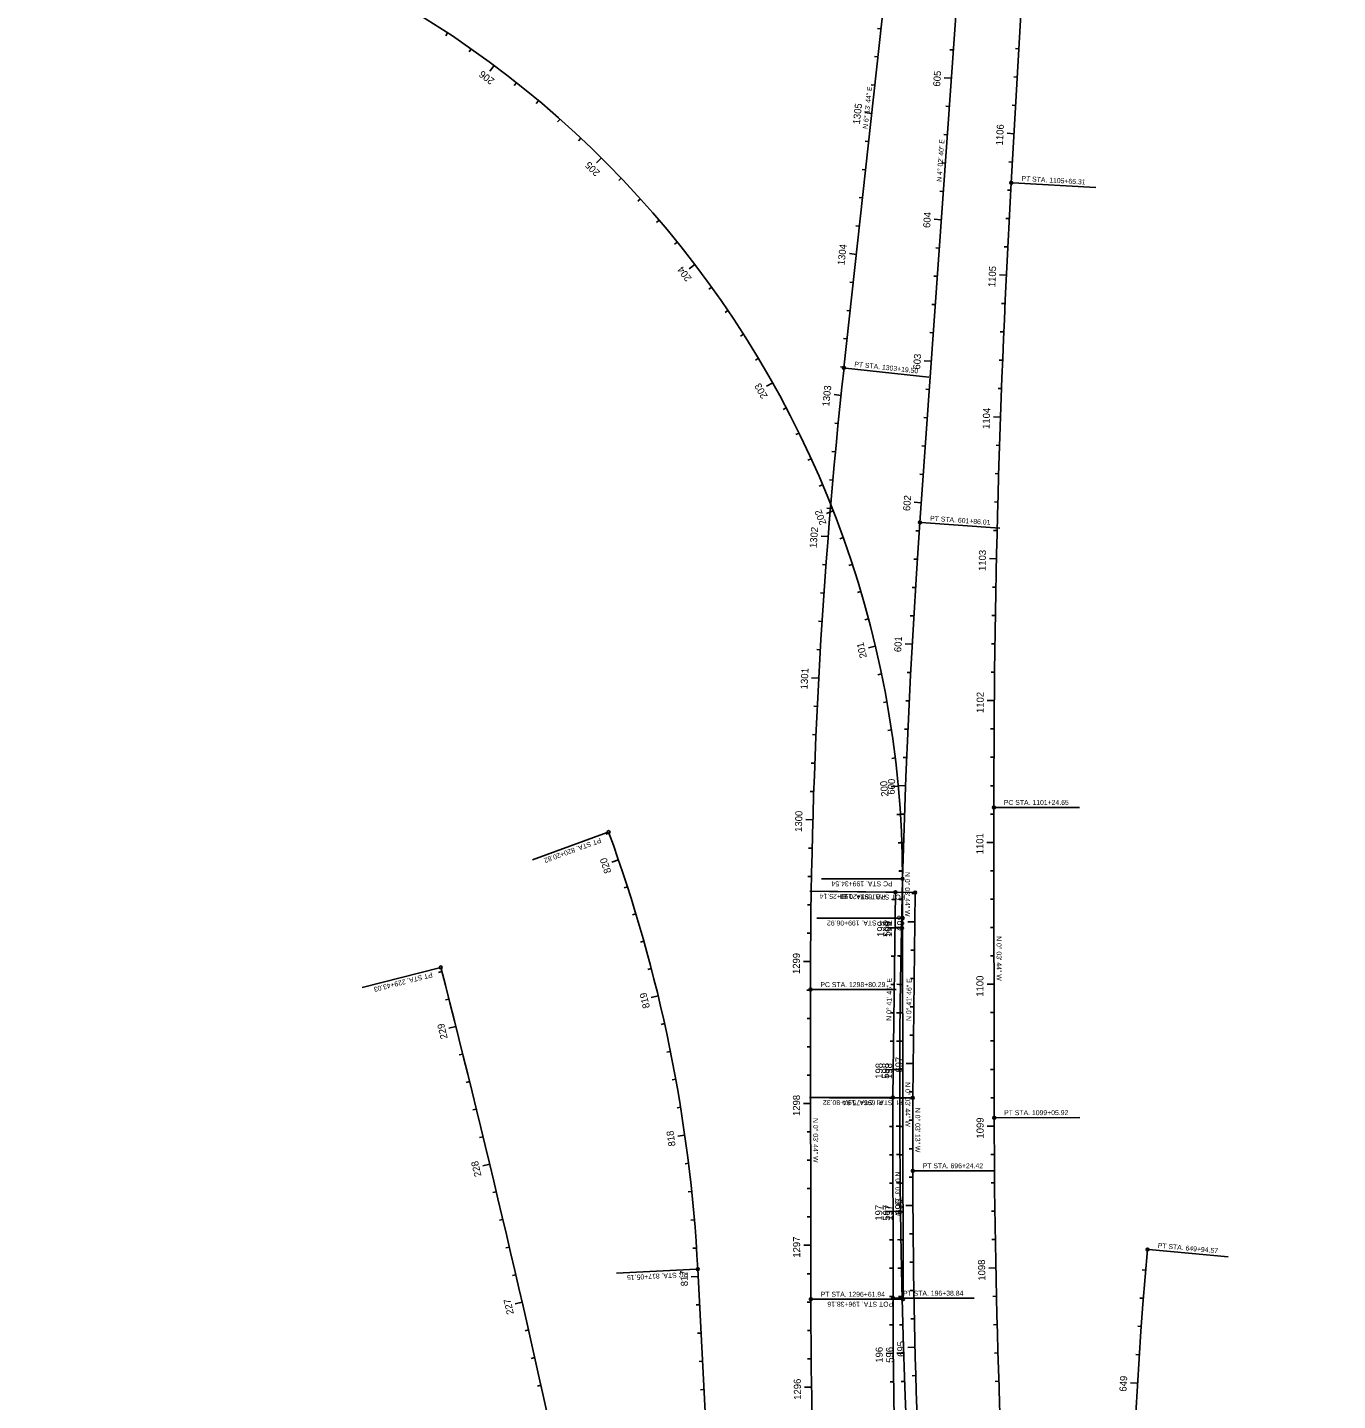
# Model space of a CAD drawing. Extents: x 919452 to 931278, y 583254 to 665650.
# Drawn here: x 928370 to 929294, y 635415 to 636383 of the extents above; entities that cross this region are included whole.
import ezdxf

# ---------------------------------------------------------------- set-up
doc = ezdxf.new("R2010")
doc.units = 0
for name, color, linetype in [('CLConst_dp', 7, 'Continuous'), ('CurveDataLabel_dp', 7, 'Continuous'), ('StationTicL_dp', 7, 'Continuous'), ('StationTicS_dp', 7, 'Continuous'), ('TextBLStation', 7, 'Continuous'), ('TextLabel', 7, 'Continuous')]:
    doc.layers.add(name, color=color, linetype=linetype)

msp = doc.modelspace()

# ---------------------------------------------------------------- linework, layer by layer
at = {"layer": 'CLConst_dp'}
for p, q in [((929063.91, 636273.75), (929152.38, 637830.35)), ((928999.45, 636034.27), (929035.97, 636550.78)), ((928945.89, 636143.25), (928986.58, 636516.04)), ((929051.88, 635614.6), (929051.64, 635833.32)), ((928987.22, 635755.38), (928987.19, 635783.01)), ((928980.38, 635628.77), (928982.14, 635773.59)), ((928994.38, 635628.7), (928996.14, 635773.42)), ((928987.51, 635486.62), (928987.22, 635755.38)), ((928922.51, 635486.55), (928922.28, 635704.9)), ((928980.51, 635487.29), (928980.38, 635628.77)), ((928994.43, 635577.17), (928994.38, 635628.7)), ((928856.53, 635243.73), (928842.76, 635507.87))]:
    msp.add_line(p, q, dxfattribs=at)
for centre, radius, start, end in [((928270.99, 635782.23), 716.2, 0.06217, 82.06007), ((936667.07, 635841.59), 7615.44, 176.746791, 180.062174), ((932922.28, 635709.24), 4000, 173.771, 180.06217), ((934714.76, 635630.15), 5729.58, 175.955434, 198.89818), ((927786.65, 635452.81), 1057.54, 2.98469, 20.08694), ((919023.27, 633253.37), 9949, 9.590734, 14.358327), ((934757.45, 635620.79), 5705.58, 180.06217, 188.19915), ((934313.46, 635582.15), 5319.04, 180.05369, 188.30596), ((932014.36, 635260.36), 2866.29, 174.76849, 187.10964), ((933567.21, 635491.59), 4644.7, 180.06217, 187.81416), ((933567.17, 635491.59), 4586.66, 180.05369, 186.8847)]:
    msp.add_arc(centre, radius, start, end, dxfattribs=at)
at = {"layer": 'CurveDataLabel_dp'}
for p, q in [((929064.9, 636273.7), (929123.58, 636270.36)), ((928946.88, 636143.15), (929005.84, 636136.71)), ((929000.44, 636034.2), (929055.93, 636030.28)), ((929052.64, 635833.32), (929112.1, 635833.39)), ((928778.92, 635815.67), (928726.09, 635796.35)), ((928986.19, 635783), (928929.99, 635782.94)), ((928981.14, 635773.6), (928921.85, 635774.32)), ((928995.14, 635773.43), (928935.73, 635774.15)), ((928986.22, 635755.38), (928926.79, 635755.32)), ((928660.53, 635720.33), (928606.03, 635706.38)), ((928923.28, 635704.9), (928982.69, 635704.97)), ((928979.38, 635628.77), (928921.6, 635628.72)), ((928993.38, 635628.69), (928935.74, 635628.64)), ((929052.88, 635614.6), (929112.27, 635614.66)), ((928995.43, 635577.17), (929051.68, 635577.22)), ((929161.01, 635521.62), (929216.87, 635516.5)), ((928841.76, 635507.82), (928785.52, 635504.89)), ((928923.51, 635486.55), (928982.77, 635486.62)), ((928986.51, 635486.62), (928927.15, 635486.56)), ((928981.51, 635487.29), (929037.63, 635487.35))]:
    msp.add_line(p, q, dxfattribs=at)
for centre in [(929063.91, 636273.75), (928945.89, 636143.25), (928999.45, 636034.27), (929051.64, 635833.32), (928779.86, 635816.01), (928987.19, 635783.01), (928982.14, 635773.59), (928996.14, 635773.42), (928987.22, 635755.38), (928661.5, 635720.58), (928922.28, 635704.9), (928980.38, 635628.77), (928994.38, 635628.7), (929051.88, 635614.6), (928994.43, 635577.17), (929160.01, 635521.71), (928842.76, 635507.87), (928922.51, 635486.55), (928980.51, 635487.29), (928987.51, 635486.62)]:
    msp.add_circle(centre, 1, dxfattribs=at)
at = {"layer": 'StationTicL_dp'}
for p, q in [((928699.03, 636356.45), (928696.04, 636352.44)), ((929021.59, 636347.48), (929016.61, 636347.84)), ((928965.48, 636322.69), (928960.51, 636323.23)), ((929065.88, 636308.39), (929060.88, 636308.67)), ((928774.78, 636291.29), (928771.26, 636287.74)), ((929014.54, 636247.73), (929009.55, 636248.08)), ((928954.63, 636223.28), (928949.66, 636223.82)), ((928840.72, 636216.22), (928836.75, 636213.19)), ((929060.48, 636208.53), (929055.49, 636208.78)), ((929007.49, 636147.98), (929002.5, 636148.33)), ((928895.58, 636132.71), (928891.22, 636130.26)), ((928943.82, 636123.87), (928938.85, 636124.39)), ((929056.32, 636108.62), (929051.32, 636108.8)), ((929000.43, 636048.23), (928995.45, 636048.58)), ((928938.28, 636042.37), (928933.62, 636040.56)), ((928934.7, 636024.29), (928929.72, 636024.68)), ((929053.47, 636008.66), (929048.47, 636008.77)), ((928967.99, 635946.97), (928963.12, 635945.82)), ((928994.02, 635948.44), (928989.03, 635948.71)), ((928928.07, 635924.51), (928923.08, 635924.78)), ((929051.93, 635908.68), (929046.93, 635908.72)), ((928984.13, 635848.37), (928979.15, 635847.9)), ((928989.34, 635848.55), (928984.34, 635848.74)), ((928923.94, 635824.6), (928918.94, 635824.74)), ((929051.67, 635808.68), (929046.67, 635808.67)), ((928786.82, 635796.39), (928782.09, 635794.77)), ((928981.84, 635748.45), (928976.84, 635748.51)), ((928986.4, 635748.59), (928981.4, 635748.7)), ((928987.23, 635748.46), (928982.23, 635748.46)), ((928995.89, 635752.74), (928990.89, 635752.8)), ((928922.31, 635724.61), (928917.31, 635724.63)), ((929051.77, 635708.68), (929046.77, 635708.67)), ((928814.79, 635700.42), (928809.93, 635699.25)), ((928672.08, 635678.87), (928667.23, 635677.65)), ((928994.67, 635652.75), (928989.67, 635652.81)), ((928980.62, 635648.45), (928975.62, 635648.52)), ((928985.21, 635648.6), (928980.21, 635648.62)), ((928987.34, 635648.46), (928982.34, 635648.46)), ((928922.37, 635624.61), (928917.37, 635624.61)), ((928833.58, 635602.24), (928828.63, 635601.54)), ((929051.89, 635608.68), (929046.89, 635608.67)), ((928695.97, 635581.76), (928691.11, 635580.59)), ((928980.46, 635548.46), (928975.46, 635548.45)), ((928985.76, 635548.6), (928980.76, 635548.53)), ((928987.45, 635548.46), (928982.45, 635548.46)), ((928994.51, 635552.75), (928989.51, 635552.72)), ((928922.47, 635524.61), (928917.47, 635524.61)), ((929052.97, 635508.68), (929047.98, 635508.59)), ((928843.02, 635502.73), (928838.03, 635502.47)), ((928718.89, 635484.42), (928714.01, 635483.3)), ((928980.71, 635448.46), (928975.72, 635448.41)), ((928988.05, 635448.63), (928983.06, 635448.47)), ((928996, 635452.76), (928991, 635452.64)), ((929152.95, 635427.41), (929147.95, 635427.7)), ((928923, 635424.62), (928918, 635424.54))]:
    msp.add_line(p, q, dxfattribs=at)
at = {"layer": 'StationTicS_dp'}
for p, q in [((928666.31, 636379.45), (928664.93, 636377.36)), ((928971.99, 636382.34), (928969.5, 636382.61)), ((928682.83, 636368.18), (928681.39, 636366.13)), ((929023, 636367.43), (929020.51, 636367.61)), ((929069.28, 636368.29), (929066.78, 636368.43)), ((928969.82, 636362.46), (928967.33, 636362.73)), ((929068.15, 636348.32), (929065.65, 636348.47)), ((928714.89, 636344.27), (928713.35, 636342.31)), ((928967.65, 636342.57), (928965.16, 636342.84)), ((928730.41, 636331.66), (928728.81, 636329.74)), ((929020.18, 636327.53), (929017.69, 636327.71)), ((929067.01, 636328.36), (929064.51, 636328.5)), ((928745.58, 636318.62), (928743.92, 636316.74)), ((928760.37, 636305.16), (928758.66, 636303.33)), ((928963.31, 636302.81), (928960.82, 636303.08)), ((929018.77, 636307.58), (929016.28, 636307.76)), ((928961.14, 636282.93), (928958.65, 636283.2)), ((929017.36, 636287.63), (929014.87, 636287.81)), ((929064.74, 636288.42), (929062.24, 636288.56)), ((928788.8, 636277.02), (928786.99, 636275.3)), ((928802.41, 636262.37), (928800.55, 636260.7)), ((928958.97, 636263.05), (928956.48, 636263.32)), ((929015.95, 636267.68), (929013.46, 636267.86)), ((929063.61, 636268.45), (929061.11, 636268.59)), ((928815.61, 636247.35), (928813.71, 636245.72)), ((928956.8, 636243.16), (928954.31, 636243.43)), ((929062.51, 636248.48), (929060.02, 636248.62)), ((928828.38, 636231.96), (928826.44, 636230.39)), ((929013.13, 636227.78), (929010.64, 636227.96)), ((929061.47, 636228.51), (929058.97, 636228.64)), ((928952.46, 636203.4), (928949.97, 636203.67)), ((929011.72, 636207.83), (929009.23, 636208.01)), ((928852.62, 636200.14), (928850.59, 636198.69)), ((928864.06, 636183.74), (928861.99, 636182.34)), ((928950.29, 636183.52), (928947.8, 636183.79)), ((929010.31, 636187.88), (929007.81, 636188.06)), ((929059.54, 636188.56), (929057.05, 636188.67)), ((928875.04, 636167.03), (928872.93, 636165.68)), ((928948.12, 636163.64), (928945.63, 636163.91)), ((929008.9, 636167.93), (929006.4, 636168.11)), ((929058.66, 636168.58), (929056.16, 636168.68)), ((928885.55, 636150.01), (928883.4, 636148.73)), ((928945.95, 636143.75), (928943.46, 636144.03)), ((929057.82, 636148.59), (929055.33, 636148.69)), ((929006.08, 636128.03), (929003.58, 636128.21)), ((929057.04, 636128.61), (929054.55, 636128.7)), ((928905.12, 636115.13), (928902.91, 636113.97)), ((929004.67, 636108.08), (929002.17, 636108.26)), ((928914.17, 636097.3), (928911.92, 636096.2)), ((928941.8, 636103.97), (928939.31, 636104.22)), ((929003.25, 636088.13), (929000.76, 636088.31)), ((929055.64, 636088.63), (929053.14, 636088.71)), ((928922.72, 636079.21), (928920.44, 636078.18)), ((928939.88, 636084.06), (928937.39, 636084.3)), ((929001.84, 636068.18), (928999.35, 636068.36)), ((929055.02, 636068.64), (929052.52, 636068.72)), ((928930.75, 636060.9), (928928.45, 636059.93)), ((928938.05, 636064.15), (928935.56, 636064.37)), ((929054.45, 636048.65), (929051.95, 636048.72)), ((928936.33, 636044.22), (928933.84, 636044.43)), ((928999.03, 636028.28), (928996.53, 636028.45)), ((929053.93, 636028.66), (929051.43, 636028.72)), ((928945.28, 636023.64), (928942.93, 636022.8)), ((928997.67, 636008.33), (928995.18, 636008.49)), ((928933.18, 636004.34), (928930.68, 636004.53)), ((928951.76, 636004.72), (928949.38, 636003.94)), ((928996.39, 635988.37), (928993.89, 635988.52)), ((929053.05, 635988.67), (929050.56, 635988.72)), ((928931.75, 635984.4), (928929.26, 635984.57)), ((928957.71, 635985.62), (928955.31, 635984.91)), ((928930.42, 635964.44), (928927.93, 635964.6)), ((928963.12, 635966.37), (928960.7, 635965.73)), ((928995.17, 635968.4), (928992.67, 635968.55)), ((929052.69, 635968.67), (929050.19, 635968.71)), ((928929.2, 635944.48), (928926.7, 635944.62)), ((929052.39, 635948.67), (929049.89, 635948.71)), ((928972.32, 635927.45), (928969.87, 635926.94)), ((928992.95, 635928.47), (928990.45, 635928.6)), ((929052.13, 635928.67), (929049.63, 635928.7)), ((928927.05, 635904.54), (928924.55, 635904.66)), ((928976.1, 635907.81), (928973.64, 635907.37)), ((928991.94, 635908.49), (928989.44, 635908.61)), ((928926.12, 635884.56), (928923.62, 635884.67)), ((928979.33, 635888.07), (928976.86, 635887.7)), ((928991.01, 635888.51), (928988.51, 635888.63)), ((929051.78, 635888.68), (929049.28, 635888.69)), ((928925.29, 635864.57), (928922.79, 635864.67)), ((928982.01, 635868.25), (928979.53, 635867.95)), ((928990.14, 635868.53), (928987.64, 635868.64)), ((929051.68, 635868.68), (929049.18, 635868.69)), ((928924.57, 635844.59), (928922.07, 635844.67)), ((929051.64, 635848.68), (929049.14, 635848.68)), ((928985.7, 635828.43), (928983.21, 635828.27)), ((928988.61, 635828.56), (928986.12, 635828.65)), ((929051.64, 635828.68), (929049.14, 635828.67)), ((928780.14, 635815.24), (928777.79, 635814.39)), ((928923.41, 635804.6), (928920.91, 635804.66)), ((928986.71, 635808.45), (928984.21, 635808.36)), ((928987.96, 635808.57), (928985.46, 635808.65)), ((928987.17, 635788.46), (928984.67, 635788.44)), ((928987.37, 635788.58), (928984.87, 635788.65)), ((929051.69, 635788.68), (929049.19, 635788.67)), ((928793.14, 635777.42), (928790.76, 635776.65)), ((928922.99, 635784.61), (928920.49, 635784.66)), ((928982.08, 635768.45), (928979.58, 635768.48)), ((928986.85, 635768.59), (928984.35, 635768.65)), ((928987.21, 635768.46), (928984.71, 635768.46)), ((928996.13, 635772.74), (928993.63, 635772.77)), ((929051.71, 635768.68), (929049.21, 635768.67)), ((928799.1, 635758.33), (928796.7, 635757.6)), ((928922.66, 635764.61), (928920.16, 635764.65)), ((929051.73, 635748.68), (929049.23, 635748.67)), ((928804.69, 635739.13), (928802.29, 635738.45)), ((928922.43, 635744.61), (928919.93, 635744.63)), ((928981.59, 635728.45), (928979.09, 635728.48)), ((928986.02, 635728.6), (928983.52, 635728.64)), ((928987.25, 635728.46), (928984.75, 635728.46)), ((928995.65, 635732.74), (928993.15, 635732.77)), ((929051.75, 635728.68), (929049.25, 635728.67)), ((928662.25, 635717.64), (928659.83, 635717.02)), ((928809.93, 635719.82), (928807.51, 635719.19)), ((928981.35, 635708.45), (928978.85, 635708.48)), ((928985.71, 635708.6), (928983.21, 635708.63)), ((928987.27, 635708.46), (928984.77, 635708.46)), ((928995.4, 635712.75), (928992.9, 635712.78)), ((928667.19, 635698.26), (928664.76, 635697.64)), ((928922.28, 635704.61), (928919.78, 635704.61)), ((928981.11, 635688.45), (928978.61, 635688.48)), ((928985.48, 635688.6), (928982.98, 635688.63)), ((928987.3, 635688.46), (928984.8, 635688.46)), ((928995.16, 635692.75), (928992.66, 635692.78)), ((929051.8, 635688.68), (929049.3, 635688.67)), ((928819.29, 635680.94), (928816.85, 635680.4)), ((928922.3, 635684.61), (928919.8, 635684.61)), ((928994.92, 635672.75), (928992.42, 635672.78)), ((928676.94, 635659.46), (928674.51, 635658.86)), ((928823.42, 635661.37), (928820.97, 635660.87)), ((928922.32, 635664.61), (928919.82, 635664.61)), ((928980.86, 635668.45), (928978.36, 635668.48)), ((928985.31, 635668.6), (928982.81, 635668.62)), ((928987.32, 635668.46), (928984.82, 635668.46)), ((929051.82, 635668.68), (929049.32, 635668.67)), ((928681.75, 635640.05), (928679.33, 635639.45)), ((928827.18, 635641.72), (928824.72, 635641.28)), ((928922.34, 635644.61), (928919.84, 635644.61)), ((929051.84, 635648.68), (929049.34, 635648.67)), ((928994.43, 635632.75), (928991.93, 635632.78)), ((928686.53, 635620.63), (928684.1, 635620.04)), ((928830.57, 635622.01), (928828.1, 635621.61)), ((928980.38, 635628.46), (928977.88, 635628.45)), ((928985.18, 635628.6), (928982.68, 635628.6)), ((928987.36, 635628.46), (928984.86, 635628.46)), ((929051.86, 635628.68), (929049.36, 635628.67)), ((928994.4, 635612.75), (928991.9, 635612.75)), ((928922.39, 635604.61), (928919.89, 635604.61)), ((928980.4, 635608.46), (928977.9, 635608.45)), ((928985.22, 635608.6), (928982.72, 635608.59)), ((928987.38, 635608.46), (928984.88, 635608.46)), ((928691.27, 635601.2), (928688.84, 635600.61)), ((928994.42, 635592.75), (928991.92, 635592.75)), ((928836.22, 635582.42), (928833.74, 635582.11)), ((928922.41, 635584.61), (928919.91, 635584.61)), ((928980.42, 635588.46), (928977.92, 635588.45)), ((928985.33, 635588.6), (928982.83, 635588.58)), ((928987.4, 635588.46), (928984.9, 635588.46)), ((929051.96, 635588.68), (929049.46, 635588.66)), ((928994.44, 635572.75), (928991.94, 635572.75)), ((928838.48, 635562.55), (928835.99, 635562.29)), ((928922.43, 635564.61), (928919.93, 635564.61)), ((928980.44, 635568.46), (928977.94, 635568.45)), ((928985.51, 635568.6), (928983.01, 635568.58)), ((928987.43, 635568.46), (928984.93, 635568.46)), ((929052.11, 635568.68), (929049.61, 635568.65)), ((928700.63, 635562.31), (928698.2, 635561.73)), ((928922.45, 635544.61), (928919.95, 635544.61)), ((929052.33, 635548.68), (929049.83, 635548.65)), ((928705.26, 635542.85), (928702.82, 635542.28)), ((928840.37, 635542.64), (928837.88, 635542.42)), ((928980.48, 635528.46), (928977.98, 635528.45)), ((928986.08, 635528.61), (928983.58, 635528.56)), ((928987.47, 635528.46), (928984.97, 635528.46)), ((928994.66, 635532.75), (928992.16, 635532.73)), ((929052.62, 635528.68), (929050.12, 635528.64)), ((928709.84, 635523.39), (928707.4, 635522.82)), ((928841.88, 635522.69), (928839.38, 635522.53)), ((928922.5, 635504.61), (928920, 635504.61)), ((928980.49, 635508.46), (928977.99, 635508.45)), ((928986.47, 635508.61), (928983.97, 635508.56)), ((928987.49, 635508.46), (928984.99, 635508.46)), ((928994.88, 635512.75), (928992.38, 635512.72)), ((929158.72, 635507.19), (929156.23, 635507.41)), ((928714.38, 635503.91), (928711.95, 635503.34)), ((928980.51, 635488.46), (928978.01, 635488.45)), ((928986.93, 635488.62), (928984.43, 635488.55)), ((928987.51, 635488.46), (928985.01, 635488.46)), ((928995.18, 635492.76), (928992.68, 635492.71)), ((929053.4, 635488.69), (929050.9, 635488.63)), ((929157.07, 635487.26), (929154.58, 635487.46)), ((928844.07, 635482.75), (928841.57, 635482.62)), ((928922.52, 635484.61), (928920.02, 635484.61)), ((928980.57, 635468.46), (928978.07, 635468.44)), ((928987.45, 635468.62), (928984.96, 635468.55)), ((928995.55, 635472.76), (928993.05, 635472.71)), ((929053.9, 635468.69), (929051.4, 635468.63)), ((929155.56, 635467.32), (929153.06, 635467.5)), ((928723.35, 635464.93), (928720.91, 635464.37)), ((928845.11, 635462.78), (928842.61, 635462.65)), ((928922.59, 635464.61), (928920.09, 635464.6)), ((929054.47, 635448.7), (929051.97, 635448.63)), ((929154.18, 635447.37), (929151.69, 635447.53)), ((928727.78, 635445.42), (928725.34, 635444.87)), ((928846.15, 635442.81), (928843.65, 635442.68)), ((928922.75, 635444.61), (928920.25, 635444.59)), ((928980.95, 635428.46), (928978.45, 635428.42)), ((928988.72, 635428.64), (928986.22, 635428.55)), ((928996.53, 635432.77), (928994.03, 635432.7)), ((929055.11, 635428.71), (929052.61, 635428.63)), ((928732.16, 635425.91), (928729.73, 635425.37)), ((928847.19, 635422.83), (928844.69, 635422.7))]:
    msp.add_line(p, q, dxfattribs=at)

# ---------------------------------------------------------------- texts
at = {"layer": 'CurveDataLabel_dp'}
for s, rotation, p in [('PT STA. 1105+65.31', 356.74679, (929070.99, 636275.1)), ('PT STA. 1303+19.50', 353.771, (928953.04, 636144.23)), ('PT STA. 601+86.01', 355.95543, (929006.55, 636035.53)), ('PC STA. 1101+24.65', 0.06217, (929058.64, 635835.08)), ('PT STA. 820+20.82', 200.08694, (928773.89, 635811.96)), ('PC STA. 199+34.54', 180.06217, (928980.2, 635781.25)), ('POT STA. 199+25.14', 179.30385, (928975.12, 635771.92)), ('POT STA. 698+20.68', 179.30385, (928989.12, 635771.75)), ('POT STA. 199+06.92', 180.06217, (928980.23, 635753.62)), ('PT STA. 229+43.03', 194.35833, (928655.15, 635717.15)), ('PC STA. 1298+80.29', 0.06217, (928929.28, 635706.66)), ('PI  STA. 197+80.32', 180.05369, (928973.38, 635627.02)), ('PI  STA. 696+75.94', 180.05369, (928987.38, 635626.94)), ('PT STA. 1099+05.92', 0.06217, (929058.87, 635616.36)), ('PT STA. 696+24.42', 0.05369, (929001.43, 635578.92)), ('PT STA. 649+94.57', 354.76849, (929167.14, 635522.81)), ('PC STA. 817+05.15', 182.98469, (928835.86, 635505.76)), ('PT STA. 1296+61.94', 0.06217, (928929.51, 635488.31)), ('PT STA. 196+38.84', 0.05369, (928987.51, 635489.05)), ('POT STA. 196+38.16', 180.06217, (928980.52, 635484.86))]:
    msp.add_text(s, height=3.5, rotation=rotation, dxfattribs=at).set_placement(p)
at = {"layer": 'TextBLStation'}
for s, rotation, p in [('206', 143.29843, (928699.78, 636346.53)), ('605', 85.95543, (929013.65, 636341.46)), ('1305', 83.771, (928957.06, 636314.75)), ('1106', 86.74679, (929057.89, 636300.05)), ('205', 135.29846, (928774.17, 636281.34)), ('604', 85.95543, (929006.6, 636241.79)), ('1304', 83.771, (928946.22, 636215.42)), ('204', 127.29849, (928838.69, 636206.52)), ('1105', 87.23815, (929052.56, 636200.1)), ('603', 85.95543, (928999.54, 636141.94)), ('203', 119.29852, (928892.26, 636123.29)), ('1303', 84.05027, (928935.45, 636115.86)), ('1104', 87.99052, (929048.52, 636100.16)), ('602', 85.95543, (928992.49, 636042.19)), ('202', 111.29855, (928933.68, 636033.51)), ('1302', 85.48266, (928926.53, 636016.07)), ('1103', 88.74288, (929045.78, 636000)), ('201', 103.29858, (928962.1, 635939.28)), ('601', 86.81552, (928986.2, 635942.73)), ('1301', 86.91506, (928920.13, 635916.54)), ('1102', 89.49525, (929044.35, 635899.91)), ('600', 87.81552, (928981.6, 635842.32)), ('200', 95.29861, (928977.27, 635841.18)), ('1300', 88.34745, (928916.19, 635816.05)), ('1101', 90.06217, (929044.17, 635800.29)), ('820', 108.95914, (928781.85, 635787.79)), ('698', 89.30385, (928988.31, 635746.26)), ('199', 89.30385, (928974.26, 635742.01)), ('599', 88.81552, (928978.77, 635742.22)), ('199', 90.06217, (928979.74, 635741.92)), ('1299', 89.77985, (928914.77, 635715.86)), ('1100', 90.06217, (929044.28, 635699.9)), ('819', 103.54128, (928809.03, 635692.32)), ('229', 104.11049, (928666.4, 635670.7)), ('198', 89.30385, (928973.04, 635641.97)), ('598', 89.81552, (928977.69, 635642.05)), ('198', 90.06217, (928979.85, 635641.88)), ('697', 89.30385, (928987.1, 635646.37)), ('1298', 90.06217, (928914.87, 635615.79)), ('1099', 90.12163, (929044.4, 635599.88)), ('818', 98.12343, (928827.08, 635594.68)), ('228', 103.5346, (928690.22, 635573.62)), ('696', 90.3167, (928987.05, 635546.18)), ('197', 90.05369, (928972.96, 635541.98)), ('597', 90.81552, (928978.35, 635542.02)), ('197', 90.06217, (928979.95, 635541.98)), ('1297', 90.06217, (928914.98, 635515.89)), ('1098', 91.12584, (929045.65, 635499.72)), ('817', 92.98469, (928835.87, 635495.87)), ('227', 102.9587, (928713.03, 635476.43)), ('695', 91.39388, (928988.66, 635446.02)), ('196', 90.53884, (928973.28, 635441.85)), ('596', 91.81552, (928980.76, 635441.86)), ('1296', 90.82625, (928915.62, 635415.73)), ('649', 86.65894, (929145.08, 635421.32))]:
    msp.add_text(s, height=5, rotation=rotation, dxfattribs=at).set_placement(p)
at = {"layer": 'TextLabel'}
for s, rotation, p in [('N 6%%d 13\' 44" E', 83.771, (928962.51, 636311.63)), ('N 4%%d 02\' 40" E', 85.95543, (929014.67, 636274.38)), ('N 0%%d 03\' 44" W', 270.06217, (928988.94, 635787.82)), ('N 0%%d 03\' 44" W', 270.06217, (929053.49, 635742.59)), ('N 0%%d 41\' 46" E', 89.30385, (928979.29, 635682.89)), ('N 0%%d 41\' 46" E', 89.30385, (928993.29, 635682.76)), ('N 0%%d 03\' 44" W', 270.06217, (928989.1, 635639.63)), ('N 0%%d 03\' 13" W', 270.05369, (928996.14, 635621.56)), ('N 0%%d 03\' 44" W', 270.06217, (928924.13, 635614.35)), ('N 0%%d 03\' 13" W', 270.05369, (928982.18, 635576.66))]:
    msp.add_text(s, height=3.5, rotation=rotation, dxfattribs=at).set_placement(p)

doc.saveas('drawing.dxf')
